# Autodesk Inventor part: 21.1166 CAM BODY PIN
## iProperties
Created: 2007-03
Part Number: 21.1166 CAM BODY PIN
Document SubType Name: Modeling
Designer: Andy Moles
Material: Steel
Mass: 1.91353 g
Surface Area: 2.52707 cm^2
Volume: 0.243761 cm^3
Density: 7.85 g/cm^3
Author: Andy Moles
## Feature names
1. Base1
